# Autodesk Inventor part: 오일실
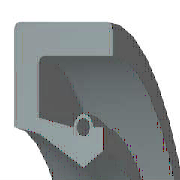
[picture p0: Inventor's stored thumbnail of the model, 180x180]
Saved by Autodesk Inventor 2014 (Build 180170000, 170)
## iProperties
IsCustomPart: 0
Company: 한국ATC센터
Created: 2014-08
Part Number: 오일실
Material: 고무
Description: 오일-실
Document SubType Name: Modeling
Standard: KS B 2804
Designer: KYOUNG IL JANG
Standards Organization: KS
Language: ko-KR
Size Designation: S - 17 30 8
Categories: <MemberInstance><Categories><Category DisplayName="샤프트 부품" InternalName="7f7aeb1f-a693-4053-b835-cee3144e0d98" Mnemonic="SHFT"><Category DisplayName="실링" Intern
Density: 0.93 g/cm^3
Appearance: 고무 - 검은색 - 버전 1.1
Author: KYOUNG IL JANG
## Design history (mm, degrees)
revolve "본체" stored, may be unused: angle "d17" = 90 deg
revolve "스프링1" stored, may be unused: angle "d18" = 90 deg
body "Solid1"
sketch "스케치1"
  geometry: L1 (0, 15)-(8, 15); L2 (8, 15)-(8, 13.75); L3 (8, 13.75)-(1.75, 13.75); L4 (0, 15)-(0, 10.6); L5 (0, 10.6)-(1.75, 10.25); L6 (1.75, 10.25)-(4.9, 8.5); L7 (4.9, 8.5)-(0, 8.5); L8 (6.3, 9.375)-(6.3, 10.6); L9 (0, 0)-(9.586, 0) reference; L10 (4.9, 8.5)-(6.3, 9.375); L11 (0, 18)-(0, -3) reference; L12 (-1.917, 0)-(11.503, 0) reference; L13 (4.2, 10.6)-(1.75, 11.09); L14 (1.75, 11.09)-(1.75, 13.75); L15 (6.3, 10.6)-(5.6, 10.6); C1 r 0.455 at (4.9, 10.6); A1 r 0.7 centre (4.9, 10.6) between (5.6, 10.6) and (4.2, 10.6)
  constraints: 26 end point, 5 horizontal alignment, 4 perpendicular, 2 centre point, 2 collinear, 2 horizontal, 2 parallel, 2 point on circle, 2 point on line, 2 vertical alignment, 1 coincident
  dimensions: "d0" = 30 diameter of L1 L9 (= SD2); "d1" = 18.75 diameter of L8.start L9 (= ABDM); "d2" = 1.25 distance of L1.end L2.end (computed from SD); "d3" = 0.91 diameter of C1 (= SPDI); "d4" = 1.4 diameter of A1 (= SPDA); "d5" = 17 diameter of L6.end L9 (= NND); "d6" = 20.5 diameter of L5.end L9 (= TKDM); "d7" = 21.2 diameter of L4.end L9 (= HLDM); "d8" = 4.9 distance from line of C1.centre L4 (= SPDST); "d9" = 6.3 distance between parallel lines of L8 L4 (= SDI); "d10" = 8 distance between parallel lines of L2 L4 (= SWDT); "d12" = 1.75 distance between parallel lines of L14 L4 (= SD)
fillet "모깎기1" dims "d11" = 0.3 (= RR)
other parameters: "SD2" = 30 [user parameter; used in 1 equation term], "SWDT" = 8 [user parameter; used in 1 equation term], "RR" = 0.3 [user parameter; used in 1 equation term], "SD" = 1.75 [user parameter; used in 2 equation terms], "NND" = 17 [user parameter; used in 1 equation term], "SPDA" = 1.4 [user parameter; used in 1 equation term], "SPDI" = 0.91 [user parameter; used in 1 equation term], "TKDM" = 20.5 [user parameter; used in 1 equation term], "HLDM" = 21.2 [user parameter; used in 1 equation term], "ABDM" = 18.75 [user parameter; used in 1 equation term], "SDI" = 6.3 [user parameter; used in 1 equation term], "SPDST" = 4.9 [user parameter; used in 1 equation term], "d13" = 0, "d14" = 0, "d15" = 0, "LAB" = 0.35 [user parameter]
